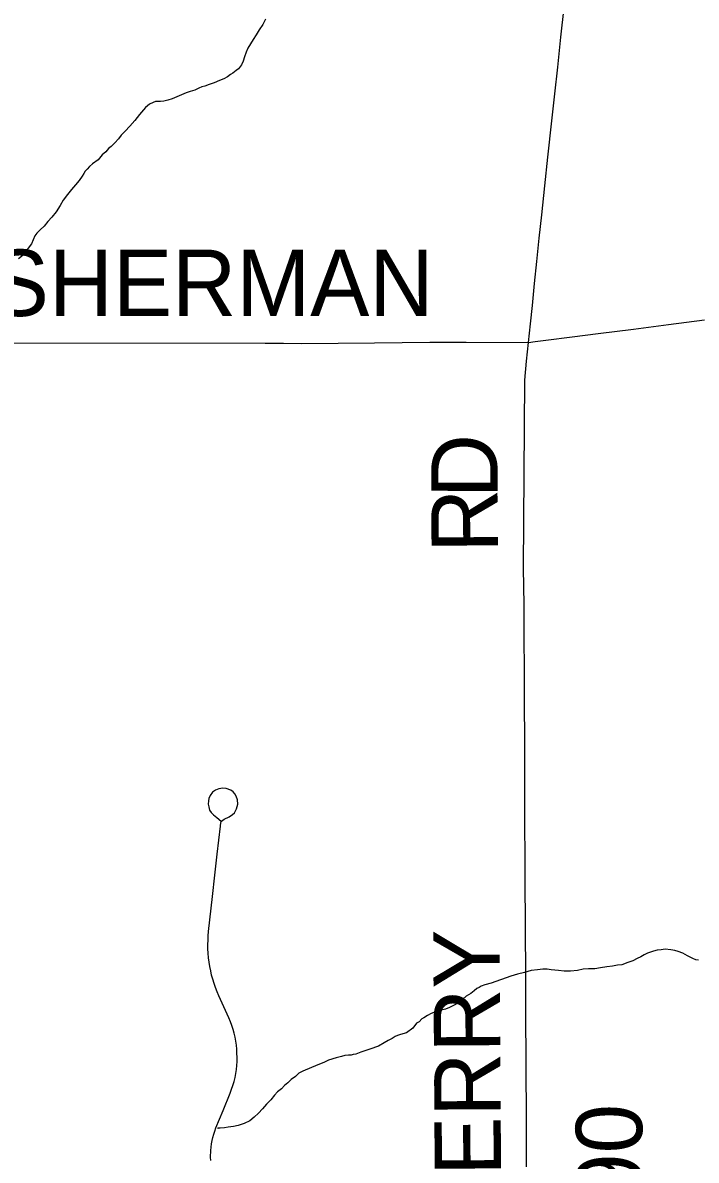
# Model space of a CAD drawing. Extents: x 103424 to 286016, y 38711 to 110967.
# Drawn here: x 112838 to 115901, y 79687 to 84863 of the extents above; entities that cross this region are included whole.
import ezdxf

# ---------------------------------------------------------------- set-up
doc = ezdxf.new("R2010")
doc.units = 0
for name, color, linetype in [('GM_X_Minor_River', 7, 'Continuous'), ('GM_X_Township_Road', 7, 'Continuous'), ('GM_X_Township_Road_Text', 7, 'Continuous')]:
    doc.layers.add(name, color=color, linetype=linetype)

msp = doc.modelspace()

# ---------------------------------------------------------------- linework, layer by layer
at = {"layer": 'GM_X_Minor_River'}
for points in [[(113941.1, 84878.5), (113929.3, 84854.1), (113913.4, 84829.7), (113899.6, 84807.4), (113885.7, 84787), (113873.8, 84766.7), (113861.9, 84746.4), (113854, 84728.1), (113846.2, 84707.8), (113840.4, 84687.6), (113832.5, 84671.3), (113818.5, 84653), (113808.5, 84644.8), (113792.5, 84632.6), (113782.5, 84626.4), (113768.5, 84616.2), (113752.4, 84607.9), (113732.3, 84599.6), (113708.2, 84589.3), (113686.1, 84581), (113666, 84574.7), (113651.9, 84570.6), (113637.8, 84564.4), (113619.7, 84556.1), (113599.6, 84549.8), (113581.5, 84543.6), (113517.2, 84516.7), (113497.1, 84510.4), (113478.9, 84506.2), (113464.8, 84504), (113454.7, 84503.9), (113440.6, 84503.8), (113430.5, 84499.7), (113414.5, 84491.4), (113396.5, 84477.1), (113368.6, 84444.5), (113346.7, 84418), (113324.8, 84391.5), (113302.8, 84369.1), (113284.9, 84350.7), (113272.9, 84334.5), (113257, 84316.1), (113239, 84299.8), (113227, 84289.6), (113215, 84275.3)], [(113215, 84275.3), (113199, 84261), (113181.1, 84238.6), (113155.1, 84220.1), (113141.1, 84207.9), (113131.1, 84195.7), (113121.1, 84187.5), (113115.2, 84177.3), (113107.3, 84165.1), (113093.4, 84144.8), (113077.4, 84124.4), (113059.5, 84104), (113041.6, 84081.6), (113021.7, 84055.2), (113007.8, 84030.8), (112990, 84002.3), (112970.1, 83977.9), (112952.1, 83957.5), (112934.2, 83937.1), (112916.2, 83920.8), (112902.3, 83904.5), (112892.3, 83892.3), (112884.4, 83874), (112876.6, 83855.8), (112862.7, 83837.4), (112850.8, 83817.1), (112838.8, 83804.9), (112818.8, 83788.5)], [(115911.5, 80597.4), (115899.4, 80599.3), (115885.1, 80605.3), (115873, 80611.2), (115860.8, 80617.1), (115850.6, 80623.1), (115840.4, 80629.1), (115818.1, 80636.9), (115804, 80640.8), (115785.7, 80644.7), (115759.5, 80646.4), (115741.3, 80644.2), (115723.2, 80642), (115707, 80637.8), (115693, 80633.6), (115678.9, 80629.5), (115664.8, 80621.2), (115648.8, 80613), (115632.7, 80604.8), (115612.6, 80594.5), (115590.5, 80586.2), (115562.4, 80575.8), (115542.2, 80573.6), (115520, 80569.3), (115493.8, 80567), (115465.6, 80562.7), (115439.4, 80558.4), (115411.1, 80558.1), (115386.9, 80555.8), (115360.7, 80549.5), (115328.4, 80547.2), (115300.2, 80546.9), (115273.9, 80550.7), (115241.5, 80552.4), (115223.3, 80556.2), (115203.1, 80556), (115178.9, 80553.8), (115150.7, 80549.5), (115120.5, 80541.1), (115088.3, 80532.7), (115058.1, 80524.3), (114967.6, 80493.1), (114939.4, 80484.7), (114923.3, 80478.5), (114913.3, 80472.3), (114903.2, 80468.2), (114891.2, 80458), (114875.2, 80445.7), (114855.2, 80433.4), (114839.2, 80419.1), (114819.2, 80402.7), (114797.1, 80390.4), (114779, 80382.1), (114760.9, 80373.9), (114740.8, 80369.6), (114730.7, 80367.5), (114714.6, 80361.3), (114694.5, 80355), (114678.5, 80344.8), (114662.4, 80334.5), (114652.4, 80330.4), (114640.4, 80316.1), (114628.4, 80309.9), (114612.5, 80287.5), (114582.4, 80267)], [(114582.4, 80267), (114556.3, 80258.7), (114542.2, 80254.5), (114532.1, 80250.4), (114518.1, 80240.1), (114500, 80231.9), (114482, 80221.6), (114455.9, 80205.2), (114415.7, 80192.6), (114389.6, 80182.3), (114375.5, 80178.1), (114353.3, 80169.8), (114341.2, 80167.7), (114331.2, 80165.5), (114319.1, 80165.4), (114302.9, 80163.2), (114286.8, 80159), (114262.7, 80152.7), (114228.4, 80142.3), (114206.3, 80132), (114180.2, 80121.6), (114111.9, 80092.6), (114093.8, 80082.4), (114077.8, 80068.1), (114057.8, 80053.7), (114043.8, 80039.5), (114027.8, 80027.2), (114013.9, 80010.9), (113995.9, 79998.6), (113981.9, 79982.3), (113966, 79961.9), (113946, 79941.5), (113928.1, 79921.1), (113910.1, 79900.8), (113890.2, 79882.4), (113870.2, 79866), (113844, 79853.6), (113817.9, 79845.3), (113795.7, 79841), (113771.5, 79836.8), (113755.4, 79834.6), (113735.2, 79832.3), (113725.1, 79832.2), (113723.1, 79830.2)]]:
    msp.add_lwpolyline(points, dxfattribs=at)
at = {"layer": 'GM_X_Township_Road'}
for points in [[(115129, 79657.3), (115128.5, 79822.4), (115126.8, 80168.8), (115126.4, 80317.2), (115126, 80465.5), (115124.3, 80806.4), (115123.2, 80908), (115122.4, 81073.1), (115121.8, 81207.4), (115121.2, 81341.6), (115120.7, 81506.7), (115119.7, 81856.8), (115118.8, 82124.3), (115118.4, 82213.6), (115116.9, 82297.4), (115115.3, 82381.2), (115122, 83236.9), (115129, 83322.9), (115137.5, 83407.8), (115146.6, 83491.9), (115155.6, 83576), (115165.4, 83676.1), (115175.2, 83776.3), (115186.6, 83882.5), (115198.1, 83988.6), (115211.9, 84120.1), (115225.8, 84251.6), (115243.9, 84415.7), (115257.4, 84538.4), (115270.9, 84661.1), (115285.5, 84796.3), (115300.2, 84931.5)], [(115137.5, 83407.8), (115168.4, 83411.6), (115217.1, 83418.4), (115336.2, 83433.5), (115455.3, 83448.7), (115615, 83468.7), (115774.7, 83488.8), (115938.3, 83510.3)], [(112593.1, 83405.7), (113939.6, 83404.7), (114023.3, 83404.2), (114107, 83403.5), (114272, 83405), (114437.1, 83406.5), (114563.3, 83407.7), (114689.6, 83408.8), (114854.6, 83408.4), (115137.5, 83407.8)], [(113692.9, 79684.9), (113692.1, 79700.1), (113692.7, 79730.6), (113693.9, 79745.7), (113696, 79760.8), (113698.7, 79775.8), (113702, 79790.6), (113706, 79805.3), (113710.8, 79819.7), (113716.4, 79834), (113748.8, 79913.2), (113781.1, 79992.4), (113787.7, 80009.7), (113793.5, 80027.2), (113798.8, 80045), (113803.1, 80062.9), (113806.6, 80081.1), (113809.6, 80099.4), (113811.7, 80117.7), (113812.9, 80136.2), (113811.9, 80191.6), (113810, 80210), (113807.2, 80228.3), (113803.9, 80246.5), (113799.7, 80264.5), (113794.6, 80282.3), (113788.8, 80299.9), (113782.3, 80317.2), (113775, 80334.2), (113729.5, 80435.2), (113721.7, 80453.6), (113714.4, 80472.2), (113707.9, 80491.1), (113701.8, 80510.2), (113696.8, 80529.5), (113692.3, 80549.1), (113688.3, 80568.7), (113685.3, 80588.4), (113682.8, 80608.3), (113681, 80628.2), (113680, 80648.2), (113681.3, 80708.2), (113683.1, 80728.2), (113700.5, 80887.2), (113711.4, 80983.4), (113722.2, 81079.6), (113736.3, 81207.4), (113739, 81223), (113741.9, 81230), (113753.3, 81238.4), (113776.2, 81248.7), (113791.5, 81259.5), (113800.3, 81267.8), (113810, 81285.9), (113815.2, 81306.4), (113814.2, 81325.9), (113808.8, 81342.7), (113802.1, 81353.9), (113794.6, 81362.7), (113784.5, 81370.3), (113762.1, 81378.4), (113747.7, 81379.5), (113729.9, 81376.1), (113714.3, 81371.2), (113700.9, 81361), (113689.6, 81346.9), (113684.5, 81332.4), (113682.2, 81322), (113680.3, 81307), (113683.2, 81294.6), (113687.4, 81280.1), (113694.2, 81269.1), (113705.2, 81258.5), (113720.6, 81246), (113739.3, 81230)]]:
    msp.add_lwpolyline(points, dxfattribs=at)

# ---------------------------------------------------------------- texts
at = {"layer": 'GM_X_Township_Road_Text'}
for s, height, rotation, p in [('SHERMAN', 301.87, 0, (112687.2, 83528.1)), ('D', 301.9, 89.8907, (114997.1, 82699.1)), ('R', 301.9, 90.4918, (114999.2, 82452)), ('SPERRY', 301.87, 90.3643, (115016.8, 79078.3)), ('T-90', 301.87, 90.3535, (115659.5, 79113.5))]:
    msp.add_text(s, height=height, rotation=rotation, dxfattribs=at).set_placement(p)

doc.saveas('drawing.dxf')
